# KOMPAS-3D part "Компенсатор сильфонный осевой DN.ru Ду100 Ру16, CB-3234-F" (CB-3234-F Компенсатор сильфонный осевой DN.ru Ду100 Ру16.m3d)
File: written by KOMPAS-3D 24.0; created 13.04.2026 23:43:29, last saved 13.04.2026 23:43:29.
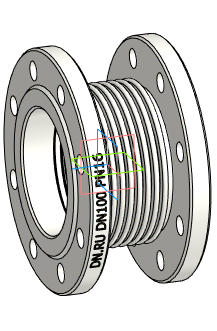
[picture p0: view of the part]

Document properties: Автор: DN.RU; Полное имя файла: D:\PROJECT CAD\DN.RU\...198(ACTUALE). CB-3234-F Компенсатор сильфонный осевой DN.ru\Исходники\DN100\CB-3234-F Компенсатор сильфонный осевой DN.ru Ду100 Ру16.m3d

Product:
- Body: Твердое тело1  | qty 1
    Масса: 9.934047
- Part/product: Компенсатор сильфонный осевой DN.ru Ду100 Ру16  | designation CB-3234-F
    Масса: 8.2
    Раздел спецификации: Прочие изделия
    Комментарий: D140-02116
    Примечание: D140-02116
    additional columns: Типовые

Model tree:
1. Твердое тело1  (labels: Твердое тело1)

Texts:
  CB-3234-F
